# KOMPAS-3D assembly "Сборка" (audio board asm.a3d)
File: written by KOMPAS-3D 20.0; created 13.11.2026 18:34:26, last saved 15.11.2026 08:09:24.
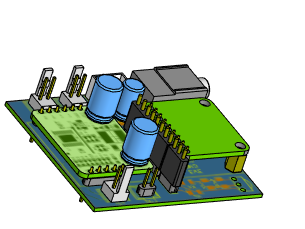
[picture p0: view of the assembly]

Document properties: Полное имя файла: D:\RicWork\Project-EPS32\box_compas\аудио\audio board asm.a3d

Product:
- Part/product: Сборка
    Масса: 0.0902695
  - Component [assembly]: Сборка  | Масса: 0.0184861; source file: ..\усилитель\HT8698_asm.a3d
  - Component [detail]: Деталь  | Масса: 0.0145552; source file: ..\разъемы\PJ-306BM.m3d
  - Component [assembly]: Сборка  | Масса: 0.0110383; source file: ..\SD card\Adafruit_Micro_SD_SPI_or_SDIO asm +.a3d
  - Component [detail]: Деталь  | Масса: 0.0248425; source file: audio_pcb.m3d
  - Component [detail]: Деталь  | Масса: 0.00102673; source file: ..\разъемы\pls_8.m3d
  - Component [detail]: Деталь  | Масса: 0.00246148; source file: ..\разъемы\pbs_8.m3d
  - Component [detail]: Деталь  | Масса: 0.000374976; source file: ..\разъемы\pls_3.m3d
  - Component [detail]: Деталь  | Масса: 0.000955835; source file: ..\разъемы\pbs_3.m3d
  - Component [detail]: Деталь  | qty 3  | Масса: 0.000929543; source file: ..\разъемы\WF-2 (DS1070-2 M).m3d
  - Component [detail]: Деталь  | Масса: 0.000244624; source file: ..\разъемы\pls_2.m3d
  - Component [detail]: Деталь  | Масса: 0.00117184; source file: ..\разъемы\B3B-XH-A.m3d
  - Component [assembly]: Сборка  | Масса: 0.00967177; source file: ..\цап ацп\pcm5102A_asm_pj.a3d
  - Component [detail]: Деталь  | Масса: 0.00265163; source file: ..\прочее\470mkf 6.3x11 p2.5 (10YXJ470M6.3X11 (К50-35 имп.)).m3d

Referenced files in D:\RicWork\Project-EPS32\box_compas\SD card\: Adafruit_Micro_SD_SPI_or_SDIO asm +.a3d
Referenced files in D:\RicWork\Project-EPS32\box_compas\разъемы\: PJ-306BM.m3d, pls_8.m3d, pbs_8.m3d, pls_3.m3d, pbs_3.m3d, WF-2 (DS1070-2 M).m3d, pls_2.m3d, B3B-XH-A.m3d
Referenced files in D:\RicWork\Project-EPS32\box_compas\аудио\: audio_pcb.m3d
Referenced files in D:\RicWork\Project-EPS32\box_compas\усилитель\: HT8698_asm.a3d
Referenced files in D:\RicWork\Project-EPS32\box_compas\цап ацп\: pcm5102A_asm_pj.a3d
Referenced files in D:\RicWork\Project-EPS32\box_compas\прочее\: 470mkf 6.3x11 p2.5 (10YXJ470M6.3X11 (К50-35 имп.)).m3d
Referenced files in D:\myProjects\Progect_esp32\box_compas\разъемы\: WF-2 (DS1070-2 M).m3d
